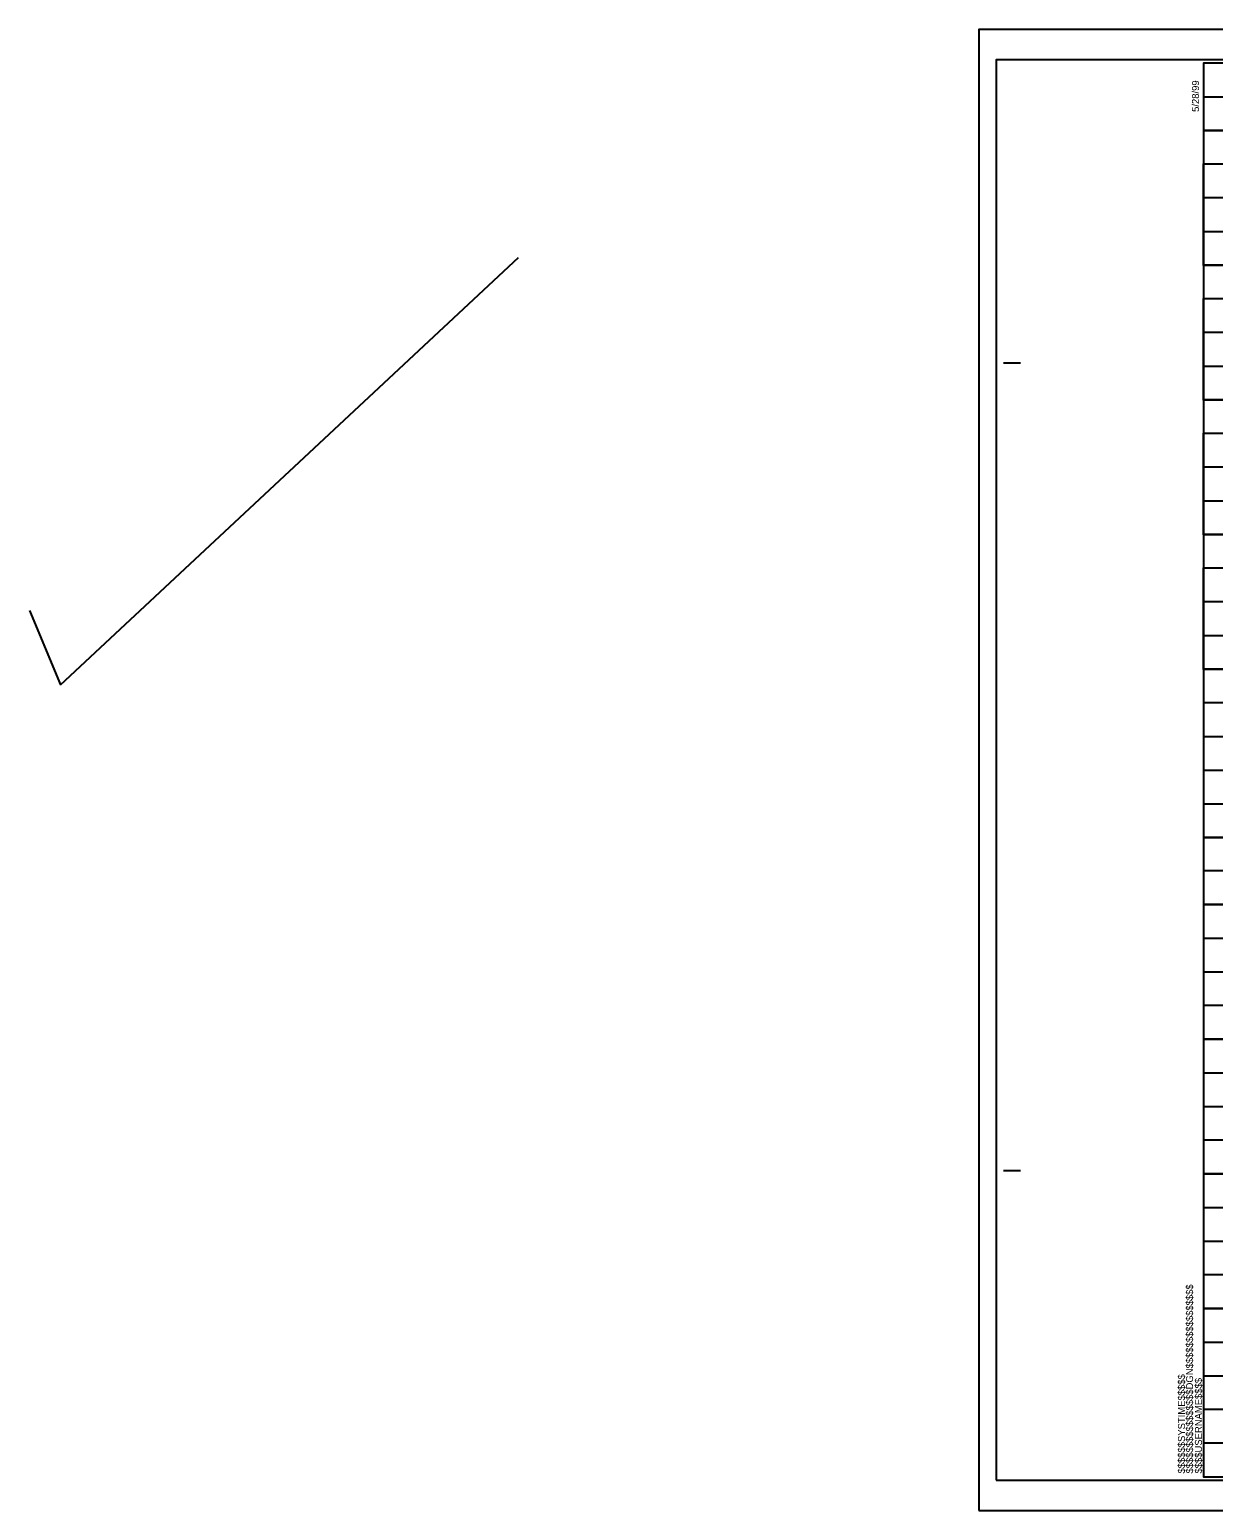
# Model space of a CAD drawing. Extents: x 1648157 to 1650776, y 832691 to 834781.
# Drawn here: x 1648157 to 1649037, y 832691 to 833791 of the extents above; entities that cross this region are included whole.
import ezdxf

# ---------------------------------------------------------------- set-up
doc = ezdxf.new("R2010")
doc.units = 0
for name, color, linetype in [('Prop Grid Mask', 7, 'Continuous'), ('Sheet Cutting Line CELL', 7, 'Continuous'), ('Sheet DOT Grid CELL', 7, 'Continuous'), ('Sheet Plot Border Inside CELL', 7, 'Continuous'), ('Sheet Plot Border Outside CELL', 7, 'Continuous'), ('Sheet Profile CELL', 7, 'Continuous'), ('Sheet Profile Grid Major CELL', 7, 'Continuous'), ('Sheet Profile Grid Middle CELL', 7, 'Continuous')]:
    doc.layers.add(name, color=color, linetype=linetype)

msp = doc.modelspace()

# ---------------------------------------------------------------- linework, layer by layer
at = {"layer": 'Prop Grid Mask'}
for p, q in [((1648180.1, 833304.3), (1648520.3, 833621.7)), ((1648157.1, 833359.5), (1648180.1, 833304.3))]:
    msp.add_line(p, q, dxfattribs=at)
at = {"layer": 'Sheet Cutting Line CELL'}
for p, q in [((1650546.3, 833791), (1648862.3, 833791)), ((1648862.3, 833791), (1648862.3, 832691)), ((1648862.3, 832691), (1650546.3, 832691))]:
    msp.add_line(p, q, dxfattribs=at)
at = {"layer": 'Sheet DOT Grid CELL'}
for p, q in [((1650329.2, 833716), (1649029.3, 833716)), ((1650329.2, 833666), (1649029.3, 833666)), ((1650329.3, 833616), (1649029.3, 833616)), ((1650529.3, 833566), (1649029.3, 833566)), ((1650529.3, 833516), (1649029.3, 833516)), ((1650529.3, 833466), (1649029.3, 833466)), ((1650529.3, 833416), (1649029.3, 833416)), ((1650529.3, 833366), (1649029.3, 833366)), ((1650529.3, 833316), (1649029.3, 833316)), ((1649029.3, 833241), (1650529.2, 833241)), ((1649029.3, 833191), (1650529.2, 833191)), ((1649029.3, 833141), (1650529.2, 833141)), ((1649029.3, 833091), (1650529.2, 833091)), ((1649029.3, 833041), (1650529.2, 833041)), ((1649029.3, 832991), (1650529.2, 832991)), ((1649029.3, 832941), (1650529.2, 832941)), ((1649029.3, 832891), (1650529.2, 832891)), ((1649029.3, 832841), (1650529.2, 832841)), ((1649029.3, 832791), (1650529.2, 832791))]:
    msp.add_line(p, q, dxfattribs=at)
at = {"layer": 'Sheet Plot Border Inside CELL'}
msp.add_lwpolyline([(1648875.3, 832713.5), (1650541.8, 832713.5), (1650541.8, 833768.6), (1648875.3, 833768.6)], close=True, dxfattribs=at)
at = {"layer": 'Sheet Plot Border Outside CELL'}
msp.add_lwpolyline([(1648862.3, 832691), (1650546.3, 832691), (1650546.3, 833791), (1648862.3, 833791)], close=True, dxfattribs=at)
at = {"layer": 'Sheet Profile CELL'}
for p, q in [((1648880.8, 833543.5), (1648893.3, 833543.5)), ((1649029.3, 833266), (1650529.3, 833266)), ((1649029.3, 833241), (1650529.3, 833241)), ((1648880.8, 832943.5), (1648893.3, 832943.5)), ((1650529.3, 832741), (1649029.3, 832741)), ((1649029.3, 832716), (1650529.3, 832716)), ((1649029.3, 832716), (1649029.3, 832716)), ((1649029.3, 832716), (1649029.3, 832716)), ((1649029.3, 832716), (1649029.3, 832716)), ((1649029.3, 832716), (1649029.3, 832716)), ((1649029.3, 832716), (1649029.3, 832716)), ((1649029.3, 832716), (1649029.3, 832716)), ((1649029.3, 832716), (1649029.3, 832716))]:
    msp.add_line(p, q, dxfattribs=at)
msp.add_lwpolyline([(1650529.3, 833766), (1649029.3, 833766), (1649029.3, 832716), (1650529.3, 832716)], close=True, dxfattribs=at)
at = {"layer": 'Sheet Profile Grid Major CELL'}
msp.add_line((1649029.3, 832741), (1649029.3, 832741), dxfattribs=at)
for points in [[(1649029.2, 833716), (1650329.2, 833716)], [(1650329.2, 833666), (1649029.2, 833666), (1649029.2, 833616), (1650329.2, 833616)], [(1650529.2, 833566), (1649029.2, 833566), (1649029.2, 833516), (1650529.2, 833516)], [(1650529.2, 833466), (1649029.2, 833466), (1649029.2, 833416), (1650529.2, 833416)], [(1650529.2, 833366), (1649029.2, 833366), (1649029.2, 833366), (1649029.2, 833316), (1650529.2, 833316)], [(1650529.3, 833191), (1649029.3, 833191)], [(1650529.3, 833141), (1649029.3, 833141), (1649029.3, 833091), (1650529.3, 833091)], [(1650529.3, 833041), (1649029.3, 833041), (1649029.3, 832991), (1650529.3, 832991)], [(1650529.3, 832941), (1649029.3, 832941), (1649029.3, 832891), (1650529.3, 832891)], [(1650529.3, 832841), (1649029.3, 832841), (1649029.3, 832841), (1649029.3, 832791), (1650529.3, 832791)], [(1650529.3, 832741), (1649029.3, 832741)]]:
    msp.add_lwpolyline(points, dxfattribs=at)
at = {"layer": 'Sheet Profile Grid Middle CELL'}
msp.add_line((1649029.2, 833741), (1650179.2, 833741), dxfattribs=at)
for points in [[(1650329.2, 833691), (1649029.2, 833691), (1649029.2, 833641), (1650329.2, 833641)], [(1650529.2, 833591), (1649029.2, 833591), (1649029.2, 833541), (1650354.2, 833541)], [(1650529.2, 833491), (1649029.2, 833491), (1649029.2, 833441), (1650529.2, 833441)], [(1650529.2, 833391), (1649029.2, 833391), (1649029.2, 833341), (1650529.2, 833341)], [(1650529.2, 833291), (1649029.2, 833291)], [(1649029.3, 833216), (1650529.3, 833216)], [(1650529.3, 833166), (1649029.3, 833166), (1649029.3, 833116), (1650529.3, 833116)], [(1650529.3, 833066), (1649029.3, 833066), (1649029.3, 833016), (1650529.3, 833016)], [(1650529.3, 832966), (1649029.3, 832966), (1649029.3, 832916), (1650529.3, 832916)], [(1650529.3, 832866), (1649029.3, 832866), (1649029.3, 832816), (1650529.3, 832816)], [(1650529.3, 832766), (1649029.3, 832766)]]:
    msp.add_lwpolyline(points, dxfattribs=at)

# ---------------------------------------------------------------- texts
at = {"layer": 'Sheet Profile CELL'}
for s, p in [('5/28/99', (1649026, 833729.9)), ('$$$$$$$$$$$$$$$$DGN$$$$$$$$$$$$$$$$', (1649021.6, 832718.4)), ('$$$$$$SYSTIME$$$$$', (1649015.6, 832718.4)), ('$$$$USERNAME$$$$', (1649028.2, 832718.4))]:
    msp.add_text(s, height=5.25, rotation=90, dxfattribs=at).set_placement(p)

doc.saveas('drawing.dxf')
